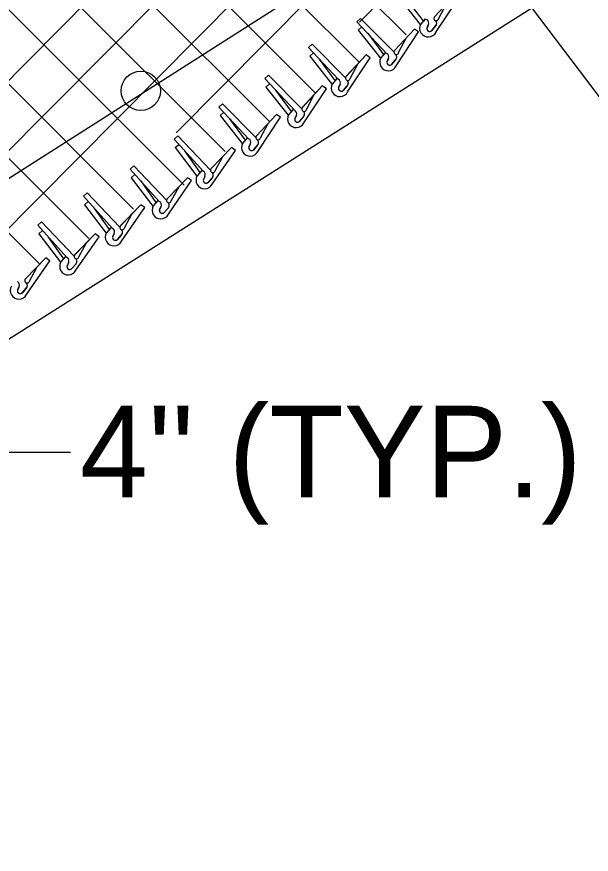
# Model space of a CAD drawing. Extents: x 0 to 1270, y 0 to 830.
# Drawn here: x 729.87 to 760.97, y 632.14 to 677.48 of the extents above; entities that cross this region are included whole.
import ezdxf

# ---------------------------------------------------------------- set-up
doc = ezdxf.new("R2010")
doc.units = 0
for name, color, linetype in [('CT_Dimensions', 7, 'Continuous'), ('sb_Chainlink Fence', 7, 'Continuous'), ('sb_Earth', 7, 'Continuous'), ('sb_Existing Structural Steel', 7, 'Continuous')]:
    doc.layers.add(name, color=color, linetype=linetype)

msp = doc.modelspace()

# ---------------------------------------------------------------- linework, layer by layer
at = {"layer": 'CT_Dimensions'}
for p, q in [((777.673, 651.622), (754.726, 681.98)), ((729.219, 653.909), (732.774, 653.909))]:
    msp.add_line(p, q, dxfattribs=at)
at = {"layer": 'sb_Chainlink Fence'}
for p, q in [((725.985, 666.765), (880.45, 822.372)), ((726.216, 662.794), (880.266, 818.188)), ((705.822, 650.219), (870.725, 816.56)), ((738.503, 671.19), (880.44, 814.366)), ((748.417, 677.192), (881.936, 811.877)), ((712.617, 714.835), (750.949, 676.502)), ((710.214, 713.207), (748.417, 675.003)), ((707.803, 711.587), (746.025, 673.365)), ((705.372, 709.988), (743.573, 671.787)), ((703.018, 708.311), (741.15, 670.179)), ((700.58, 706.719), (738.94, 668.358)), ((698.217, 705.051), (736.197, 667.072)), ((695.781, 703.457), (733.768, 665.469)), ((693.408, 701.799), (731.097, 664.11)), ((750.71, 678.759), (751.879, 677.258)), ((750.512, 678.58), (751.717, 677.061)), ((753.564, 678.641), (752.478, 677.474)), ((752.566, 676.645), (753.787, 678.489)), ((752.706, 677.373), (753.113, 678.148)), ((748.284, 677.213), (748.482, 677.392)), ((750.294, 675.569), (748.482, 677.392)), ((751.985, 677.371), (751.74, 677.082)), ((751.989, 677.376), (751.741, 677.083)), ((749.895, 675.498), (748.284, 677.213)), ((748.351, 676.75), (748.549, 676.929)), ((751.723, 677.049), (751.707, 677.013)), ((751.741, 677.083), (751.723, 677.049)), ((752.08, 676.881), (752.162, 677.058)), ((752.162, 677.052), (752.08, 676.885)), ((752.543, 676.98), (752.32, 676.716)), ((752.341, 676.738), (752.543, 676.98)), ((748.351, 676.75), (749.556, 675.232)), ((748.87, 676.584), (749.717, 675.428)), ((751.403, 676.811), (750.317, 675.644)), ((751.403, 676.811), (750.323, 675.651)), ((750.405, 674.816), (751.625, 676.659)), ((751.625, 676.659), (751.403, 676.811)), ((745.662, 675.812), (745.86, 675.991)), ((747.671, 674.167), (745.86, 675.991)), ((750.545, 675.543), (750.951, 676.319)), ((747.272, 674.097), (745.662, 675.812)), ((745.728, 675.349), (745.926, 675.528)), ((749.824, 675.542), (749.578, 675.252)), ((749.828, 675.546), (749.58, 675.253)), ((745.728, 675.349), (746.933, 673.83)), ((746.248, 675.182), (747.095, 674.026)), ((748.78, 675.41), (747.694, 674.242)), ((748.78, 675.41), (747.701, 674.249)), ((747.783, 673.414), (749.003, 675.257)), ((749.003, 675.257), (748.78, 675.41)), ((749.561, 675.219), (749.546, 675.183)), ((749.58, 675.253), (749.561, 675.219)), ((749.919, 675.051), (750.001, 675.229)), ((750, 675.222), (749.919, 675.055)), ((750.382, 675.15), (750.159, 674.887)), ((750.18, 674.908), (750.382, 675.15)), ((747.922, 674.142), (748.329, 674.917)), ((743.292, 674.134), (743.49, 674.313)), ((744.903, 672.419), (743.292, 674.134)), ((745.302, 672.49), (743.49, 674.313)), ((747.202, 674.14), (746.956, 673.851)), ((747.205, 674.144), (746.957, 673.852)), ((743.359, 673.671), (743.557, 673.85)), ((746.411, 673.732), (745.325, 672.565)), ((746.411, 673.732), (745.331, 672.572)), ((746.633, 673.58), (746.411, 673.732)), ((746.939, 673.818), (746.923, 673.781)), ((746.957, 673.852), (746.939, 673.818)), ((747.296, 673.65), (747.378, 673.827)), ((747.378, 673.821), (747.296, 673.654)), ((747.759, 673.748), (747.536, 673.485)), ((747.557, 673.507), (747.759, 673.748)), ((743.359, 673.671), (744.564, 672.153)), ((743.878, 673.505), (744.725, 672.349)), ((745.413, 671.737), (746.633, 673.58)), ((745.553, 672.464), (745.959, 673.24)), ((740.807, 672.592), (741.005, 672.771)), ((742.418, 670.877), (740.807, 672.592)), ((742.817, 670.948), (741.005, 672.771)), ((744.832, 672.463), (744.586, 672.173)), ((744.836, 672.467), (744.588, 672.174)), ((740.874, 672.129), (741.072, 672.308)), ((740.874, 672.129), (742.079, 670.61)), ((741.393, 671.962), (742.241, 670.806)), ((743.926, 672.19), (742.84, 671.022)), ((743.926, 672.19), (742.847, 671.029)), ((742.928, 670.194), (744.149, 672.037)), ((744.149, 672.037), (743.926, 672.19)), ((744.569, 672.14), (744.554, 672.104)), ((744.588, 672.174), (744.569, 672.14)), ((744.927, 671.972), (745.009, 672.149)), ((745.008, 672.143), (744.927, 671.976)), ((745.39, 672.071), (745.167, 671.808)), ((745.188, 671.829), (745.39, 672.071)), ((743.068, 670.922), (743.475, 671.697)), ((738.387, 670.862), (738.588, 671.037)), ((740.362, 669.177), (738.588, 671.037)), ((739.962, 669.114), (738.387, 670.862)), ((738.444, 670.397), (738.645, 670.572)), ((742.084, 670.598), (742.069, 670.561)), ((742.103, 670.632), (742.084, 670.598)), ((742.347, 670.92), (742.101, 670.631)), ((742.351, 670.925), (742.103, 670.632)), ((742.442, 670.43), (742.524, 670.607)), ((742.523, 670.601), (742.442, 670.434)), ((742.905, 670.528), (742.682, 670.265)), ((742.703, 670.287), (742.905, 670.528)), ((738.444, 670.397), (739.617, 668.854)), ((738.959, 670.22), (739.783, 669.047)), ((741.496, 670.396), (740.386, 669.251)), ((741.496, 670.396), (740.393, 669.258)), ((740.458, 668.421), (741.716, 670.239)), ((741.716, 670.239), (741.496, 670.396)), ((740.612, 669.146), (741.035, 669.912)), ((736.008, 669.233), (736.21, 669.408)), ((737.583, 667.485), (736.008, 669.233)), ((737.984, 667.548), (736.21, 669.408)), ((739.892, 669.159), (739.64, 668.875)), ((739.895, 669.163), (739.641, 668.876)), ((736.065, 668.768), (736.267, 668.943)), ((736.065, 668.768), (737.239, 667.225)), ((739.118, 668.767), (738.008, 667.622)), ((739.118, 668.767), (738.015, 667.628)), ((739.337, 668.61), (739.118, 668.767)), ((739.622, 668.842), (739.606, 668.806)), ((739.641, 668.876), (739.622, 668.842)), ((739.976, 668.667), (740.062, 668.842)), ((740.061, 668.836), (739.977, 668.671)), ((740.441, 668.756), (740.213, 668.497)), ((740.234, 668.518), (740.441, 668.756)), ((736.581, 668.591), (737.404, 667.418)), ((738.08, 666.792), (739.337, 668.61)), ((738.234, 667.516), (738.656, 668.283)), ((733.477, 667.771), (733.679, 667.946)), ((735.452, 666.085), (733.679, 667.946)), ((735.052, 666.023), (733.477, 667.771)), ((733.534, 667.306), (733.736, 667.481)), ((737.514, 667.53), (737.262, 667.245)), ((737.517, 667.534), (737.263, 667.246)), ((733.534, 667.306), (734.707, 665.763)), ((734.05, 667.129), (734.873, 665.956)), ((736.586, 667.305), (735.476, 666.16)), ((736.586, 667.305), (735.483, 666.166)), ((735.548, 665.33), (736.806, 667.147)), ((736.806, 667.147), (736.586, 667.305)), ((737.244, 667.213), (737.228, 667.177)), ((737.263, 667.246), (737.244, 667.213)), ((737.598, 667.038), (737.683, 667.213)), ((737.683, 667.207), (737.598, 667.042)), ((738.063, 667.127), (737.835, 666.868)), ((737.856, 666.889), (738.063, 667.127)), ((735.703, 666.054), (736.125, 666.821)), ((731.007, 666.196), (731.208, 666.371)), ((732.582, 664.448), (731.007, 666.196)), ((732.982, 664.511), (731.208, 666.371)), ((734.982, 666.068), (734.73, 665.783)), ((734.986, 666.072), (734.732, 665.784)), ((731.064, 665.731), (731.266, 665.906)), ((731.064, 665.731), (732.237, 664.188)), ((731.58, 665.554), (732.403, 664.381)), ((734.116, 665.73), (733.006, 664.585)), ((734.116, 665.73), (733.013, 664.592)), ((733.078, 663.755), (734.336, 665.573)), ((734.336, 665.573), (734.116, 665.73)), ((734.713, 665.751), (734.696, 665.715)), ((734.732, 665.784), (734.713, 665.751)), ((735.066, 665.576), (735.152, 665.751)), ((735.152, 665.745), (735.067, 665.58)), ((735.532, 665.665), (735.303, 665.406)), ((735.324, 665.427), (735.532, 665.665)), ((733.233, 664.479), (733.655, 665.246)), ((731.439, 664.422), (730.329, 663.277)), ((731.439, 664.422), (730.336, 663.284)), ((730.4, 662.447), (731.658, 664.265)), ((731.658, 664.265), (731.439, 664.422)), ((732.243, 664.176), (732.226, 664.14)), ((732.262, 664.209), (732.243, 664.176)), ((732.512, 664.493), (732.26, 664.208)), ((732.515, 664.497), (732.262, 664.209)), ((732.596, 664.001), (732.682, 664.176)), ((732.682, 664.17), (732.597, 664.005)), ((730.555, 663.172), (730.977, 663.939)), ((733.062, 664.09), (732.833, 663.831)), ((732.854, 663.852), (733.062, 664.09)), ((729.919, 662.693), (730.004, 662.868)), ((730.004, 662.862), (729.919, 662.697)), ((730.384, 662.782), (730.156, 662.523)), ((730.177, 662.545), (730.384, 662.782))]:
    msp.add_line(p, q, dxfattribs=at)
for centre, radius, start, end in [((751.968, 677.138), 0.209, 336.423, 65.0975), ((752.58, 677.395), 0.128, 138.9611, 350.0092), ((752.147, 676.853), 0.468, 150.7128, 333.6195), ((752.224, 676.835), 0.152, 160.674, 309.1571), ((752.224, 676.835), 0.152, 162.4544, 320.0765), ((752.408, 677.121), 0.195, 313.6069, 52.174), ((752.413, 677.122), 0.192, 320.1413, 52.9449), ((749.807, 675.308), 0.209, 336.423, 65.0975), ((750.419, 675.565), 0.128, 138.9611, 350.0092), ((749.986, 675.024), 0.468, 150.7128, 333.6195), ((750.063, 675.005), 0.152, 160.674, 309.1571), ((750.063, 675.006), 0.152, 162.4544, 320.0765), ((750.247, 675.292), 0.195, 313.6069, 52.174), ((750.252, 675.292), 0.192, 320.1413, 52.9449), ((747.796, 674.164), 0.128, 138.9611, 350.0092), ((747.364, 673.622), 0.468, 150.7128, 333.6195), ((747.184, 673.907), 0.209, 336.423, 65.0975), ((747.624, 673.89), 0.195, 313.6069, 52.174), ((747.63, 673.89), 0.192, 320.1413, 52.9449), ((747.44, 673.603), 0.152, 160.674, 309.1571), ((747.441, 673.604), 0.152, 162.4544, 320.0765), ((744.815, 672.229), 0.209, 336.423, 65.0975), ((745.427, 672.486), 0.128, 138.9611, 350.0092), ((745.255, 672.213), 0.195, 313.6069, 52.174), ((745.26, 672.213), 0.192, 320.1413, 52.9449), ((744.994, 671.944), 0.468, 150.7128, 333.6195), ((745.071, 671.926), 0.152, 160.674, 309.1571), ((745.071, 671.927), 0.152, 162.4544, 320.0765), ((742.942, 670.944), 0.128, 138.9611, 350.0092), ((742.509, 670.402), 0.468, 150.7128, 333.6195), ((742.33, 670.687), 0.209, 336.423, 65.0975), ((742.77, 670.67), 0.195, 313.6069, 52.174), ((742.775, 670.67), 0.192, 320.1413, 52.9449), ((742.586, 670.383), 0.152, 160.674, 309.1571), ((742.586, 670.384), 0.152, 162.4544, 320.0765), ((740.487, 669.17), 0.128, 137.7812, 348.8293), ((740.043, 668.637), 0.468, 149.5328, 332.4395), ((739.87, 668.926), 0.209, 335.243, 63.9175), ((740.309, 668.9), 0.195, 312.4269, 50.9941), ((740.315, 668.9), 0.192, 318.9614, 51.765), ((740.119, 668.617), 0.152, 159.4941, 307.9771), ((740.12, 668.618), 0.152, 161.2745, 318.8965), ((737.491, 667.297), 0.209, 335.243, 63.9175), ((738.108, 667.541), 0.128, 137.7812, 348.8293), ((737.931, 667.271), 0.195, 312.4269, 50.9941), ((737.936, 667.271), 0.192, 318.9614, 51.765), ((737.665, 667.008), 0.468, 149.5328, 332.4395), ((737.741, 666.988), 0.152, 159.4941, 307.9771), ((737.742, 666.989), 0.152, 161.2745, 318.8965), ((734.96, 665.835), 0.209, 335.243, 63.9175), ((735.577, 666.079), 0.128, 137.7812, 348.8293), ((735.133, 665.546), 0.468, 149.5328, 332.4395), ((735.21, 665.526), 0.152, 159.4941, 307.9771), ((735.21, 665.527), 0.152, 161.2745, 318.8965), ((735.4, 665.809), 0.195, 312.4269, 50.9941), ((735.405, 665.809), 0.192, 318.9614, 51.765), ((732.663, 663.971), 0.468, 149.5328, 332.4395), ((732.49, 664.26), 0.209, 335.243, 63.9175), ((733.107, 664.504), 0.128, 137.7812, 348.8293), ((732.93, 664.234), 0.195, 312.4269, 50.9941), ((732.935, 664.234), 0.192, 318.9614, 51.765), ((732.74, 663.951), 0.152, 159.4941, 307.9771), ((732.74, 663.952), 0.152, 161.2745, 318.8965), ((730.429, 663.197), 0.128, 137.7812, 348.8293), ((729.986, 662.664), 0.468, 149.5328, 332.4395), ((729.812, 662.952), 0.209, 335.243, 63.9175), ((730.252, 662.926), 0.195, 312.4269, 50.9941), ((730.257, 662.926), 0.192, 318.9614, 51.765), ((730.062, 662.644), 0.152, 159.4941, 307.9771), ((730.062, 662.644), 0.152, 161.2745, 318.8965)]:
    msp.add_arc(centre, radius, start, end, dxfattribs=at)
at = {"layer": 'sb_Earth'}
msp.add_line((633.881, 599.502), (772.831, 687.523), dxfattribs=at)
at = {"layer": 'sb_Existing Structural Steel'}
msp.add_line((632.766, 607.059), (768.798, 693.845), dxfattribs=at)
msp.add_circle((736.587, 673.469), 1.06, dxfattribs=at)

# ---------------------------------------------------------------- texts
at = {"layer": 'CT_Dimensions'}
msp.add_text("4'' (TYP.)", height=4.95, rotation=360, dxfattribs=at).set_placement((733.288, 651.47))

doc.saveas('drawing.dxf')
